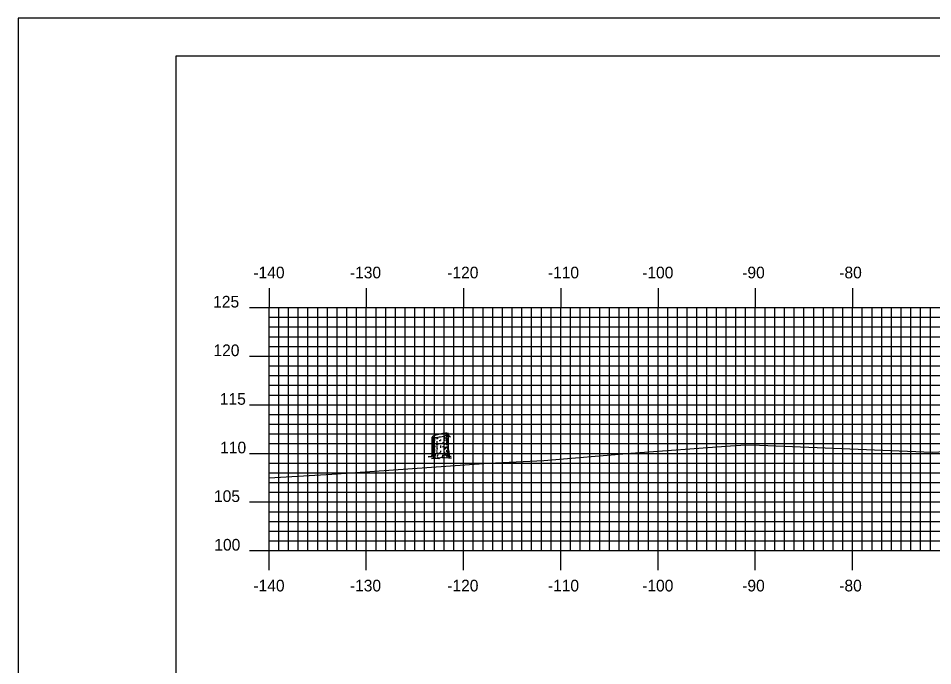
# Model space of a CAD drawing. Extents: x 1685192 to 1685536, y 461260 to 461480.
# Drawn here: x 1685192.4 to 1685286.5, y 461413.4 to 461480 of the extents above; entities that cross this region are included whole.
import ezdxf

# ---------------------------------------------------------------- set-up
doc = ezdxf.new("R2010")
doc.units = 0
for name, color, linetype in [('BORDER', 7, 'Continuous'), ('H_V ANNOTATION', 7, 'Continuous'), ('M_Trees_Conifer_Pay', 7, 'Continuous'), ('MAJOR', 7, 'Continuous'), ('MINOR', 7, 'Continuous'), ('PLOT BOUNDARY', 7, 'Continuous'), ('S_Roadway_Centerline', 7, 'Continuous')]:
    doc.layers.add(name, color=color, linetype=linetype)

msp = doc.modelspace()

# ---------------------------------------------------------------- linework, layer by layer
at = {"layer": 'BORDER'}
msp.add_lwpolyline([(1685208.629, 461266.072), (1685528.629, 461266.072), (1685528.629, 461476.072), (1685208.629, 461476.072)], close=True, dxfattribs=at)
at = {"layer": 'M_Trees_Conifer_Pay'}
for p, q in [((1685235.013, 461435.164), (1685235.013, 461436.886)), ((1685235.06, 461436.849), (1685235.06, 461436.378)), ((1685235.118, 461436.838), (1685235.118, 461436.74)), ((1685235.118, 461436.666), (1685235.118, 461436.462)), ((1685235.244, 461436.83), (1685235.244, 461436.598)), ((1685235.464, 461436.85), (1685235.464, 461436.682)), ((1685236.26, 461436.892), (1685236.26, 461436.693)), ((1685236.488, 461437.088), (1685236.488, 461436.865)), ((1685236.488, 461436.777), (1685236.488, 461436.729)), ((1685236.605, 461437.149), (1685236.605, 461436.987)), ((1685236.605, 461436.919), (1685236.605, 461436.791)), ((1685236.677, 461435.575), (1685236.677, 461437.222)), ((1685235.06, 461436.313), (1685235.06, 461436.005)), ((1685235.06, 461435.958), (1685235.06, 461435.466)), ((1685235.118, 461436.404), (1685235.118, 461436.204)), ((1685235.118, 461436.157), (1685235.118, 461435.821)), ((1685235.118, 461435.768), (1685235.118, 461435.632)), ((1685235.244, 461436.557), (1685235.244, 461436.483)), ((1685235.244, 461436.079), (1685235.244, 461435.941)), ((1685235.464, 461436.445), (1685235.464, 461436.208)), ((1685235.464, 461435.964), (1685235.464, 461435.811)), ((1685235.464, 461435.768), (1685235.464, 461435.595)), ((1685235.869, 461436.619), (1685235.869, 461436.523)), ((1685235.869, 461436.005), (1685235.869, 461435.931)), ((1685235.869, 461435.906), (1685235.869, 461435.758)), ((1685236.26, 461436.635), (1685236.26, 461436.546)), ((1685236.26, 461436.199), (1685236.26, 461436.094)), ((1685236.26, 461435.727), (1685236.26, 461435.58)), ((1685236.488, 461436.394), (1685236.488, 461436.262)), ((1685236.488, 461436.151), (1685236.488, 461436.042)), ((1685236.488, 461435.906), (1685236.488, 461435.764)), ((1685236.545, 461436.594), (1685236.494, 461436.534)), ((1685236.605, 461436.604), (1685236.605, 461436.268)), ((1685236.605, 461436.231), (1685236.605, 461436.069)), ((1685236.605, 461436.021), (1685236.605, 461435.805)), ((1685236.605, 461435.774), (1685236.605, 461435.7)), ((1685235.06, 461435.412), (1685235.06, 461435.164)), ((1685235.118, 461435.533), (1685235.118, 461435.155)), ((1685235.244, 461435.669), (1685235.244, 461435.527)), ((1685235.244, 461435.265), (1685235.244, 461435.171)), ((1685235.244, 461434.771), (1685235.407, 461434.835)), ((1685235.464, 461435.317), (1685235.464, 461435.164)), ((1685235.869, 461435.466), (1685235.869, 461435.313)), ((1685236.26, 461435.348), (1685236.26, 461435.26)), ((1685236.488, 461435.537), (1685236.488, 461435.365)), ((1685236.605, 461435.659), (1685236.605, 461435.486)), ((1685235.681, 461434.707), (1685235.555, 461434.771))]:
    msp.add_line(p, q, dxfattribs=at)
for points in [[(1685236.46, 461436.682), (1685236.43, 461436.598), (1685236.426, 461436.53), (1685236.456, 461436.466)], [(1685236.494, 461436.72), (1685236.531, 461436.645), (1685236.578, 461436.702), (1685236.636, 461436.771), (1685236.728, 461436.964), (1685236.792, 461437.012), (1685236.823, 461437.018)], [(1685236.508, 461436.466), (1685236.545, 461436.594), (1685236.609, 461436.709), (1685236.639, 461436.777), (1685236.708, 461436.923)], [(1685236.723, 461436.952), (1685236.798, 461436.96), (1685236.87, 461436.861)], [(1685235.192, 461436.192), (1685235.186, 461436.287), (1685235.229, 461436.264), (1685235.229, 461436.17)], [(1685236.331, 461435.793), (1685236.344, 461435.716), (1685236.391, 461435.727), (1685236.378, 461435.893)], [(1685236.677, 461435.575), (1685236.728, 461435.313), (1685236.744, 461435.039), (1685236.802, 461434.914), (1685236.938, 461434.883), (1685236.708, 461434.846), (1685236.708, 461434.846), (1685236.714, 461434.798), (1685236.961, 461434.704), (1685236.687, 461434.72), (1685236.331, 461434.741), (1685236.01, 461434.73), (1685236.016, 461434.813), (1685235.868, 461434.73), (1685235.681, 461434.707), (1685235.705, 461434.64), (1685235.437, 461434.683), (1685235.217, 461434.656), (1685234.924, 461434.673), (1685235.213, 461434.73), (1685235.244, 461434.771), (1685235.081, 461434.829), (1685234.844, 461434.84), (1685234.603, 461434.84), (1685234.945, 461434.897), (1685234.987, 461434.977), (1685235.013, 461435.164)], [(1685235.061, 461435.117), (1685235.04, 461435.039), (1685235.019, 461434.945)], [(1685235.139, 461435.097), (1685235.145, 461434.981), (1685235.092, 461434.893), (1685235.081, 461434.829)], [(1685235.302, 461435.124), (1685235.302, 461434.992), (1685235.213, 461434.893)], [(1685235.528, 461434.883), (1685235.596, 461434.977), (1685235.622, 461435.117)], [(1685236.016, 461434.813), (1685236.09, 461434.954), (1685236.1, 461435.056)], [(1685236.267, 461435.182), (1685236.277, 461435.056), (1685236.351, 461435.012)], [(1685236.545, 461434.792), (1685236.531, 461434.93), (1685236.456, 461435.059)], [(1685236.504, 461435.286), (1685236.578, 461435.182), (1685236.582, 461435.008), (1685236.708, 461434.846)], [(1685236.603, 461435.432), (1685236.609, 461435.286), (1685236.656, 461435.218), (1685236.666, 461435.019)]]:
    msp.add_lwpolyline(points, dxfattribs=at)
for centre, radius, start, end in [((1685235.045, 461436.708), 0.0334, 163.94846, 180), ((1685235.045, 461436.708), 0.0334, 180, 196.05154), ((1685235.044, 461436.885), 0.0314, 156.51582, 169.2194), ((1685235.039, 461436.886), 0.0264, 169.2194, 180.03145), ((1685235.036, 461436.886), 0.0226, 180.03145, 191.7194), ((1685235.036, 461436.886), 0.0226, 191.7194, 203.40735), ((1685235.055, 461436.711), 0.0441, 196.05154, 210), ((1685235.064, 461436.877), 0.0527, 146.7194, 156.51582), ((1685235.039, 461436.887), 0.0264, 203.40735, 214.2194), ((1685235.043, 461436.89), 0.0314, 214.2194, 226.92298), ((1685235.071, 461436.72), 0.0624, 210, 228.74941), ((1685235.088, 461436.861), 0.0817, 132.38868, 146.7194), ((1685235.058, 461436.906), 0.0527, 226.92298, 236.7194), ((1685235.074, 461436.93), 0.0817, 236.7194, 251.05013), ((1685235.144, 461436.803), 0.172, 228.74941, 240), ((1685235.202, 461436.736), 0.251, 124.2194, 132.38868), ((1685235.129, 461437.09), 0.251, 251.05013, 259.2194), ((1685235.512, 461436.28), 0.802, 108.05939, 124.2194), ((1685235.232, 461437.631), 0.802, 259.2194, 275.37941), ((1685236.869, 461432.119), 5.179, 101.7194, 108.05939), ((1685234.821, 461441.989), 5.179, 275.37941, 281.7194), ((1685235.845, 461440.898), 4.124, 264.6955, 266.73309), ((1685236.869, 461432.119), 5.179, 95.37941, 101.7194), ((1685234.821, 461441.989), 5.179, 281.7194, 288.05939), ((1685235.845, 461440.898), 4.124, 276.23804, 278.1032), ((1685236.458, 461436.477), 0.802, 79.2194, 95.37941), ((1685236.346, 461437.381), 0.571, 278.1032, 284.36665), ((1685236.178, 461437.827), 0.802, 288.05939, 304.2194), ((1685236.346, 461437.535), 0.571, 284.43166, 292.41325), ((1685236.346, 461437.381), 0.571, 297.0237, 300), ((1685236.561, 461437.018), 0.251, 71.05013, 79.2194), ((1685236.488, 461437.372), 0.251, 304.2194, 312.38868), ((1685236.545, 461437.19), 0.172, 300, 311.25059), ((1685236.545, 461437.036), 0.172, 300, 311.25059), ((1685236.616, 461437.178), 0.0817, 56.7194, 71.05013), ((1685236.602, 461437.247), 0.0817, 312.38868, 326.7194), ((1685236.618, 461437.107), 0.0624, 311.25059, 330), ((1685236.618, 461436.953), 0.0624, 311.25059, 330), ((1685236.632, 461437.202), 0.0527, 46.92298, 56.7194), ((1685236.647, 461437.217), 0.0314, 34.2194, 46.92298), ((1685236.626, 461437.231), 0.0527, 326.7194, 336.51582), ((1685236.633, 461437.098), 0.0441, 330, 343.94846), ((1685236.633, 461436.944), 0.0441, 330, 343.94846), ((1685236.651, 461437.22), 0.0264, 23.40735, 34.2194), ((1685236.646, 461437.223), 0.0314, 336.51582, 349.2194), ((1685236.654, 461437.222), 0.0226, 11.7194, 23.40735), ((1685236.654, 461437.222), 0.0226, 0.03145, 11.7194), ((1685236.644, 461437.095), 0.0334, 343.94846, 354.21506), ((1685236.644, 461436.941), 0.0334, 343.94846, 354.21506), ((1685236.651, 461437.222), 0.0264, 349.2194, 0.03145), ((1685235.045, 461436.261), 0.0334, 163.94846, 180), ((1685235.045, 461436.261), 0.0334, 180, 196.05154), ((1685235.045, 461436.051), 0.0334, 163.94846, 180), ((1685235.045, 461436.051), 0.0334, 180, 196.05154), ((1685235.045, 461435.814), 0.0334, 163.94846, 180), ((1685235.045, 461435.814), 0.0334, 180, 196.05154), ((1685235.055, 461436.264), 0.0441, 196.05154, 210), ((1685235.055, 461436.054), 0.0441, 196.05154, 210), ((1685235.055, 461435.817), 0.0441, 196.05154, 210), ((1685235.071, 461436.273), 0.0624, 210, 228.74941), ((1685235.071, 461436.063), 0.0624, 210, 228.74941), ((1685235.071, 461435.826), 0.0624, 210, 228.74941), ((1685235.144, 461436.356), 0.172, 228.74941, 240), ((1685235.144, 461436.146), 0.172, 228.74941, 240), ((1685235.144, 461435.909), 0.172, 228.74941, 240), ((1685235.343, 461437.148), 0.571, 240, 240.33672), ((1685235.343, 461436.701), 0.571, 240, 240.33672), ((1685235.343, 461436.491), 0.571, 240, 246.85973), ((1685235.343, 461436.254), 0.571, 240, 246.85973), ((1685235.344, 461436.937), 0.571, 240, 247.05866), ((1685235.343, 461437.148), 0.571, 246.85973, 257.98457), ((1685235.343, 461436.491), 0.571, 259.27072, 261.8968), ((1685235.844, 461440.008), 4.124, 261.8968, 263.14738), ((1685235.844, 461440.218), 4.124, 264.08098, 266.66759), ((1685235.844, 461440.665), 4.124, 268.07512, 270), ((1685235.844, 461440.665), 4.124, 270, 270.35814), ((1685235.844, 461440.008), 4.124, 270, 270.35814), ((1685235.844, 461440.008), 4.124, 273.14934, 275.45691), ((1685235.845, 461440.454), 4.124, 273.70524, 275.95043), ((1685235.844, 461440.665), 4.124, 275.78493, 277.05584), ((1685235.844, 461440.218), 4.124, 277.61247, 278.1032), ((1685236.344, 461436.701), 0.571, 278.1032, 286.92962), ((1685236.346, 461436.937), 0.571, 284.44928, 297.04285), ((1685236.344, 461436.254), 0.571, 285.39827, 297.18959), ((1685236.344, 461436.701), 0.571, 297.18959, 300), ((1685236.344, 461436.491), 0.571, 297.18959, 300), ((1685236.544, 461436.356), 0.172, 300, 311.25059), ((1685236.544, 461436.146), 0.172, 300, 311.25059), ((1685236.616, 461436.273), 0.0624, 311.25059, 330), ((1685236.616, 461436.063), 0.0624, 311.25059, 330), ((1685236.632, 461436.264), 0.0441, 330, 343.94846), ((1685236.632, 461436.054), 0.0441, 330, 343.94846), ((1685236.642, 461436.261), 0.0334, 343.94846, 354.21506), ((1685236.642, 461436.051), 0.0334, 343.94846, 354.21506), ((1685236.644, 461436.497), 0.0334, 343.94846, 354.21506), ((1685235.045, 461435.617), 0.0334, 163.94846, 180), ((1685235.045, 461435.421), 0.0334, 163.94846, 180), ((1685235.045, 461435.421), 0.0334, 180, 196.05154), ((1685235.045, 461435.201), 0.0334, 163.94846, 180), ((1685235.045, 461435.201), 0.0334, 180, 196.05154), ((1685235.055, 461435.424), 0.0441, 196.05154, 210), ((1685235.055, 461435.204), 0.0441, 196.05154, 210), ((1685235.071, 461435.433), 0.0624, 210, 228.74941), ((1685235.071, 461435.213), 0.0624, 210, 228.74941), ((1685235.144, 461435.516), 0.172, 228.74941, 240), ((1685235.144, 461435.296), 0.172, 228.74941, 240), ((1685235.332, 461436.063), 0.571, 241.23686, 248.02677), ((1685235.343, 461435.861), 0.571, 240, 246.85973), ((1685235.343, 461435.641), 0.571, 240, 244.53138), ((1685235.844, 461439.158), 4.124, 262.44379, 263.51202), ((1685235.844, 461439.574), 4.124, 263.49906, 265.83975), ((1685235.844, 461439.772), 4.124, 264.71603, 266.31934), ((1685235.844, 461439.378), 4.124, 267.81166, 270), ((1685235.844, 461439.378), 4.124, 270, 270.13279), ((1685235.844, 461439.378), 4.124, 275.78493, 276.78961), ((1685235.844, 461439.158), 4.124, 277.36842, 278.1032), ((1685236.344, 461435.641), 0.571, 278.1032, 281.63703), ((1685236.344, 461435.861), 0.571, 288.50673, 297.27208), ((1685236.344, 461436.056), 0.571, 289.29072, 300), ((1685236.544, 461435.711), 0.172, 300, 311.25059), ((1685236.544, 461435.296), 0.172, 300, 311.25059), ((1685236.616, 461435.629), 0.0624, 311.25059, 330), ((1685236.616, 461435.213), 0.0624, 311.25059, 330), ((1685236.632, 461435.62), 0.0441, 330, 343.94846), ((1685236.632, 461435.204), 0.0441, 330, 343.94846), ((1685236.642, 461435.617), 0.0334, 343.94846, 354.21506), ((1685236.642, 461435.201), 0.0334, 343.94846, 354.21506)]:
    msp.add_arc(centre, radius, start, end, dxfattribs=at)
at = {"layer": 'MAJOR'}
for p, q in [((1685218.229, 461452.21), (1685218.229, 461450.206)), ((1685228.229, 461452.21), (1685228.229, 461450.206)), ((1685238.229, 461452.21), (1685238.229, 461450.206)), ((1685248.229, 461452.21), (1685248.229, 461450.206)), ((1685258.229, 461452.21), (1685258.229, 461450.206)), ((1685268.229, 461452.21), (1685268.229, 461450.206)), ((1685278.229, 461452.21), (1685278.229, 461450.206)), ((1685216.225, 461450.206), (1685218.229, 461450.206)), ((1685218.229, 461450.206), (1685498.229, 461450.206)), ((1685218.229, 461425.206), (1685218.229, 461450.206)), ((1685218.229, 461425.206), (1685218.229, 461450.206)), ((1685218.229, 461450.206), (1685498.229, 461450.206)), ((1685228.229, 461425.206), (1685228.229, 461450.206)), ((1685238.229, 461425.206), (1685238.229, 461450.206)), ((1685248.229, 461425.206), (1685248.229, 461450.206)), ((1685258.229, 461425.206), (1685258.229, 461450.206)), ((1685268.229, 461425.206), (1685268.229, 461450.206)), ((1685278.229, 461425.206), (1685278.229, 461450.206)), ((1685216.225, 461445.206), (1685218.229, 461445.206)), ((1685218.229, 461445.206), (1685498.229, 461445.206)), ((1685216.225, 461440.206), (1685218.229, 461440.206)), ((1685218.229, 461440.206), (1685498.229, 461440.206)), ((1685216.225, 461435.206), (1685218.229, 461435.206)), ((1685218.229, 461435.206), (1685498.229, 461435.206)), ((1685216.225, 461430.206), (1685218.229, 461430.206)), ((1685218.229, 461430.206), (1685498.229, 461430.206)), ((1685216.225, 461425.206), (1685218.229, 461425.206)), ((1685218.229, 461425.206), (1685498.229, 461425.206)), ((1685218.229, 461425.206), (1685498.229, 461425.206)), ((1685218.229, 461423.202), (1685218.229, 461425.206)), ((1685228.229, 461423.202), (1685228.229, 461425.206)), ((1685238.229, 461423.202), (1685238.229, 461425.206)), ((1685248.229, 461423.202), (1685248.229, 461425.206)), ((1685258.229, 461423.202), (1685258.229, 461425.206)), ((1685268.229, 461423.202), (1685268.229, 461425.206)), ((1685278.229, 461423.202), (1685278.229, 461425.206))]:
    msp.add_line(p, q, dxfattribs=at)
at = {"layer": 'MINOR'}
for p, q in [((1685219.229, 461425.206), (1685219.229, 461450.206)), ((1685220.229, 461425.206), (1685220.229, 461450.206)), ((1685221.229, 461425.206), (1685221.229, 461450.206)), ((1685222.229, 461425.206), (1685222.229, 461450.206)), ((1685223.229, 461425.206), (1685223.229, 461450.206)), ((1685224.229, 461425.206), (1685224.229, 461450.206)), ((1685225.229, 461425.206), (1685225.229, 461450.206)), ((1685226.229, 461425.206), (1685226.229, 461450.206)), ((1685227.229, 461425.206), (1685227.229, 461450.206)), ((1685229.229, 461425.206), (1685229.229, 461450.206)), ((1685230.229, 461425.206), (1685230.229, 461450.206)), ((1685231.229, 461425.206), (1685231.229, 461450.206)), ((1685232.229, 461425.206), (1685232.229, 461450.206)), ((1685233.229, 461425.206), (1685233.229, 461450.206)), ((1685234.229, 461425.206), (1685234.229, 461450.206)), ((1685235.229, 461425.206), (1685235.229, 461450.206)), ((1685236.229, 461425.206), (1685236.229, 461450.206)), ((1685237.229, 461425.206), (1685237.229, 461450.206)), ((1685239.229, 461425.206), (1685239.229, 461450.206)), ((1685240.229, 461425.206), (1685240.229, 461450.206)), ((1685241.229, 461425.206), (1685241.229, 461450.206)), ((1685242.229, 461425.206), (1685242.229, 461450.206)), ((1685243.229, 461425.206), (1685243.229, 461450.206)), ((1685244.229, 461425.206), (1685244.229, 461450.206)), ((1685245.229, 461425.206), (1685245.229, 461450.206)), ((1685246.229, 461425.206), (1685246.229, 461450.206)), ((1685247.229, 461425.206), (1685247.229, 461450.206)), ((1685249.229, 461425.206), (1685249.229, 461450.206)), ((1685250.229, 461425.206), (1685250.229, 461450.206)), ((1685251.229, 461425.206), (1685251.229, 461450.206)), ((1685252.229, 461425.206), (1685252.229, 461450.206)), ((1685253.229, 461425.206), (1685253.229, 461450.206)), ((1685254.229, 461425.206), (1685254.229, 461450.206)), ((1685255.229, 461425.206), (1685255.229, 461450.206)), ((1685256.229, 461425.206), (1685256.229, 461450.206)), ((1685257.229, 461425.206), (1685257.229, 461450.206)), ((1685259.229, 461425.206), (1685259.229, 461450.206)), ((1685260.229, 461425.206), (1685260.229, 461450.206)), ((1685261.229, 461425.206), (1685261.229, 461450.206)), ((1685262.229, 461425.206), (1685262.229, 461450.206)), ((1685263.229, 461425.206), (1685263.229, 461450.206)), ((1685264.229, 461425.206), (1685264.229, 461450.206)), ((1685265.229, 461425.206), (1685265.229, 461450.206)), ((1685266.229, 461425.206), (1685266.229, 461450.206)), ((1685267.229, 461425.206), (1685267.229, 461450.206)), ((1685269.229, 461425.206), (1685269.229, 461450.206)), ((1685270.229, 461425.206), (1685270.229, 461450.206)), ((1685271.229, 461425.206), (1685271.229, 461450.206)), ((1685272.229, 461425.206), (1685272.229, 461450.206)), ((1685273.229, 461425.206), (1685273.229, 461450.206)), ((1685274.229, 461425.206), (1685274.229, 461450.206)), ((1685275.229, 461425.206), (1685275.229, 461450.206)), ((1685276.229, 461425.206), (1685276.229, 461450.206)), ((1685277.229, 461425.206), (1685277.229, 461450.206)), ((1685279.229, 461425.206), (1685279.229, 461450.206)), ((1685280.229, 461425.206), (1685280.229, 461450.206)), ((1685281.229, 461425.206), (1685281.229, 461450.206)), ((1685282.229, 461425.206), (1685282.229, 461450.206)), ((1685283.229, 461425.206), (1685283.229, 461450.206)), ((1685284.229, 461425.206), (1685284.229, 461450.206)), ((1685285.229, 461425.206), (1685285.229, 461450.206)), ((1685286.229, 461425.206), (1685286.229, 461450.206)), ((1685218.229, 461449.206), (1685498.229, 461449.206)), ((1685218.229, 461449.206), (1685220.233, 461449.206)), ((1685218.229, 461448.206), (1685498.229, 461448.206)), ((1685218.229, 461448.206), (1685220.233, 461448.206)), ((1685218.229, 461447.206), (1685498.229, 461447.206)), ((1685218.229, 461447.206), (1685220.233, 461447.206)), ((1685218.229, 461446.206), (1685498.229, 461446.206)), ((1685218.229, 461446.206), (1685220.233, 461446.206)), ((1685218.229, 461444.206), (1685498.229, 461444.206)), ((1685218.229, 461444.206), (1685220.233, 461444.206)), ((1685218.229, 461443.206), (1685498.229, 461443.206)), ((1685218.229, 461443.206), (1685220.233, 461443.206)), ((1685218.229, 461442.206), (1685498.229, 461442.206)), ((1685218.229, 461442.206), (1685220.233, 461442.206)), ((1685218.229, 461441.206), (1685498.229, 461441.206)), ((1685218.229, 461441.206), (1685220.233, 461441.206)), ((1685218.229, 461439.206), (1685498.229, 461439.206)), ((1685218.229, 461439.206), (1685220.233, 461439.206)), ((1685218.229, 461438.206), (1685498.229, 461438.206)), ((1685218.229, 461438.206), (1685220.233, 461438.206)), ((1685218.229, 461437.206), (1685498.229, 461437.206)), ((1685218.229, 461437.206), (1685220.233, 461437.206)), ((1685218.229, 461436.206), (1685498.229, 461436.206)), ((1685218.229, 461436.206), (1685220.233, 461436.206)), ((1685218.229, 461434.206), (1685498.229, 461434.206)), ((1685218.229, 461434.206), (1685220.233, 461434.206)), ((1685218.229, 461433.206), (1685220.233, 461433.206)), ((1685218.229, 461433.206), (1685498.229, 461433.206)), ((1685218.229, 461432.206), (1685498.229, 461432.206)), ((1685218.229, 461432.206), (1685220.233, 461432.206)), ((1685218.229, 461431.206), (1685498.229, 461431.206)), ((1685218.229, 461431.206), (1685220.233, 461431.206)), ((1685218.229, 461429.206), (1685498.229, 461429.206)), ((1685218.229, 461429.206), (1685220.233, 461429.206)), ((1685218.229, 461428.206), (1685498.229, 461428.206)), ((1685218.229, 461428.206), (1685220.233, 461428.206)), ((1685218.229, 461427.206), (1685498.229, 461427.206)), ((1685218.229, 461427.206), (1685220.233, 461427.206)), ((1685218.229, 461426.206), (1685498.229, 461426.206)), ((1685218.229, 461426.206), (1685220.233, 461426.206))]:
    msp.add_line(p, q, dxfattribs=at)
at = {"layer": 'PLOT BOUNDARY'}
msp.add_lwpolyline([(1685192.443, 461259.954), (1685532.443, 461259.954), (1685532.443, 461479.954), (1685192.443, 461479.954)], close=True, dxfattribs=at)
at = {"layer": 'S_Roadway_Centerline'}
msp.add_lwpolyline([(1685218.229, 461432.676), (1685224.694, 461433.067), (1685240.805, 461434.184), (1685246.481, 461434.465), (1685255.44, 461435.216), (1685265.663, 461435.989), (1685267.258, 461436.091), (1685268.667, 461436.06), (1685286.43, 461435.332), (1685288.431, 461435.437)], dxfattribs=at)

# ---------------------------------------------------------------- texts
at = {"layer": 'H_V ANNOTATION'}
for s, p in [('-140', (1685216.613, 461453.206)), ('-130', (1685226.538, 461453.206)), ('-120', (1685236.549, 461453.206)), ('-110', (1685246.892, 461453.206)), ('-100', (1685256.592, 461453.206)), ('-90', (1685266.881, 461453.206)), ('-80', (1685276.859, 461453.206)), ('125', (1685212.478, 461450.206)), ('120', (1685212.51, 461445.206)), ('115', (1685213.164, 461440.206)), ('110', (1685213.196, 461435.206)), ('105', (1685212.564, 461430.206)), ('100', (1685212.596, 461425.206)), ('-140', (1685216.613, 461421.006)), ('-130', (1685226.538, 461421.006)), ('-120', (1685236.549, 461421.006)), ('-110', (1685246.892, 461421.006)), ('-100', (1685256.592, 461421.006)), ('-90', (1685266.881, 461421.006)), ('-80', (1685276.859, 461421.006))]:
    msp.add_text(s, height=1.2, dxfattribs=at).set_placement(p)
at = {"layer": 'MAJOR'}
msp.add_text('-', height=0.012, dxfattribs=at).set_placement((1685218.22, 461425.206))

doc.saveas('drawing.dxf')
